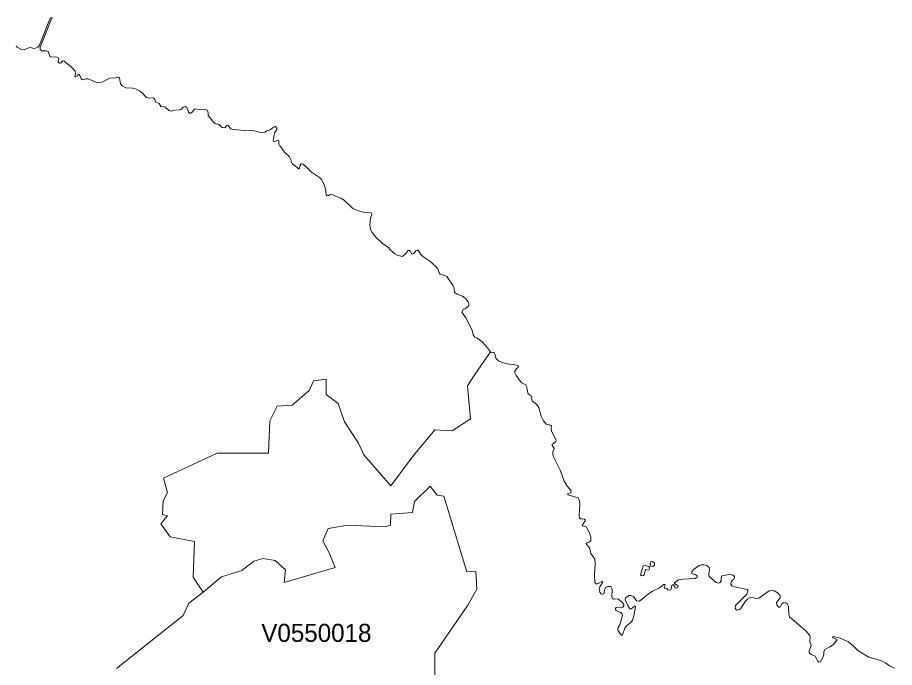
# Model space of a CAD drawing. Extents: x 369010 to 735936, y 6377141 to 6616555.
# Drawn here: x 440462 to 445317, y 6492936 to 6496537 of the extents above; entities that cross this region are included whole.
import ezdxf
from ezdxf.enums import TextEntityAlignment as Align

# ---------------------------------------------------------------- set-up
doc = ezdxf.new("R2010")
doc.units = 0
doc.header["$LTSCALE"] = 40
doc.layers.add('3', color=7, linetype='Continuous', lineweight=13)
doc.layers.add('4', color=7, linetype='Continuous')

msp = doc.modelspace()

# ---------------------------------------------------------------- linework, layer by layer
at = {"layer": '3'}
for points in [[(440645.3, 6496319.59), (440640.83, 6496323.06), (440630.74, 6496349.21), (440622.13, 6496351.86), (440595.65, 6496352.69), (440586.22, 6496360.14), (440587.87, 6496372.38), (440649.11, 6496528.45), (440653.41, 6496531.27), (440653.91, 6496534.91), (440649.77, 6496536.56), (440641.66, 6496533.25), (440581.09, 6496378.84), (440574.3, 6496373.05), (440556.26, 6496365.6), (440546.66, 6496365.93), (440532.43, 6496370.23), (440518.36, 6496367.25), (440498.33, 6496358.48), (440484.1, 6496359.14), (440460.1, 6496372.22), (440455.14, 6496377.18)], [(441928.95, 6495804.71), (441918.69, 6495824.73), (441911.57, 6495825.39), (441908.26, 6495833.67), (441909.26, 6495851.38), (441907.27, 6495854.85), (441901.81, 6495857.5), (441886.42, 6495849.72), (441877.64, 6495851.71), (441885.42, 6495895.24), (441898.33, 6495915.59), (441898, 6495924.37), (441890.55, 6495932.14), (441882.11, 6495931.81), (441863.08, 6495916.59), (441851.49, 6495911.46), (441840.74, 6495909.47), (441832.13, 6495902.02), (441820.38, 6495898.55), (441808.79, 6495898.88), (441764.61, 6495910.13), (441739.28, 6495908.48), (441656.2, 6495915.59), (441643.29, 6495920.72), (441627.24, 6495938.93), (441620.78, 6495938.27), (441610.02, 6495925.36), (441593.97, 6495928.17), (441578.58, 6495943.4), (441554.91, 6495949.85), (441548.29, 6495954.32), (441517.34, 6495993.71), (441516.68, 6496009.43), (441513.7, 6496021.35), (441501.45, 6496029.13), (441470.5, 6496027.14), (441444.35, 6496029.79), (441437.57, 6496025.49), (441430.29, 6496014.23), (441421.18, 6496005.96), (441413.41, 6496007.45), (441409.27, 6496012.08), (441399.34, 6496038.07), (441392.22, 6496043.36), (441384.77, 6496042.7), (441379.31, 6496039.72), (441367.06, 6496026.81), (441358.29, 6496024.33), (441332.47, 6496023.01), (441314.77, 6496018.54), (441300.37, 6496022.34), (441279.68, 6496040.71), (441270.74, 6496043.03), (441256.84, 6496042.7), (441245.92, 6496060.08), (441227.38, 6496068.52), (441222.91, 6496082.26), (441216.79, 6496090.7), (441207.52, 6496091.69), (441193.95, 6496089.37), (441175.91, 6496094.17), (441168.13, 6496100.3), (441154.56, 6496117.18), (441136.85, 6496130.58), (441124.27, 6496137.37), (441100.77, 6496145.81), (441062.37, 6496147.13), (441041.19, 6496158.06), (441031.75, 6496169.97), (441027.28, 6496201.92), (441021.16, 6496206.05), (441006.93, 6496202.58), (440972.17, 6496201.25), (440930.3, 6496177.75), (440910.27, 6496174.44), (440890.91, 6496179.9), (440852.18, 6496196.45), (440838.11, 6496197.45), (440824.87, 6496192.15), (440817.76, 6496192.81), (440813.29, 6496198.27), (440808.32, 6496211.18), (440800.38, 6496220.29), (440796.41, 6496220.29), (440791.28, 6496211.51), (440782.01, 6496208.04), (440779.36, 6496212.51), (440784.49, 6496232.53), (440781.01, 6496239.32), (440760, 6496261.17), (440720.77, 6496295.43), (440712.99, 6496296.09), (440701.41, 6496285), (440694.95, 6496283.84), (440687.17, 6496289.3), (440686.18, 6496293.77), (440690.15, 6496307.01), (440689.16, 6496313.8), (440680.06, 6496317.27), (440645.3, 6496319.59)], [(442170.92, 6494448.4), (442237.62, 6494397.26), (442271.71, 6494295.81), (442349.5, 6494178.63), (442378.96, 6494113.92), (442528.74, 6493942.62), (442655.02, 6494110.44), (442771.7, 6494252.94), (442867.69, 6494247.64), (442969.97, 6494313.68), (442953.75, 6494496.4), (442989.33, 6494553.99), (443079.87, 6494684.74), (443080.03, 6494685.07), (443063.81, 6494706.92), (443037.66, 6494735.22), (443009.2, 6494759.88), (442991.98, 6494766.33), (442992.31, 6494771.13), (442988.51, 6494773.12), (442984.87, 6494778.58), (442979.74, 6494803.74), (442944.81, 6494872.26), (442922.31, 6494903.87), (442930.58, 6494920.42), (442942.33, 6494924.89), (442959.71, 6494938.79), (442960.7, 6494952.36), (442957.39, 6494960.8), (442944.81, 6494978.18), (442928.76, 6494991.25), (442895.16, 6495004.83), (442884.41, 6495011.61), (442881.26, 6495017.07), (442877.95, 6495042.23), (442874.47, 6495050.67), (442839.22, 6495101.98), (442818.87, 6495111.41), (442802.65, 6495114.55), (442796.85, 6495122.33), (442789.07, 6495143.68), (442778.48, 6495157.92), (442745.22, 6495186.05), (442705.16, 6495212.53), (442694.08, 6495224.45), (442680.5, 6495247.12), (442674.38, 6495248.12), (442669.58, 6495246.46), (442655.68, 6495229.25), (442646.91, 6495226.1), (442642.77, 6495227.1), (442637.31, 6495241.33), (442628.87, 6495248.12), (442624.07, 6495246.46), (442611.99, 6495228.75), (442592.62, 6495212.86), (442567.47, 6495218.66), (442550.58, 6495227.76), (442524.43, 6495250.27), (442516.99, 6495260.03), (442480.91, 6495287.17), (442444.66, 6495320.77), (442424.97, 6495345.27), (442416.86, 6495362.15), (442411.73, 6495387.97), (442416.19, 6495424.21), (442423.31, 6495445.56), (442419.17, 6495454.17), (442376.8, 6495458.14), (442349.66, 6495464.93), (442322.52, 6495476.51), (442312.92, 6495483.3), (442270.55, 6495525), (442252.68, 6495536.26), (442225.53, 6495545.36), (442207.49, 6495554.96), (442192.27, 6495555.62), (442184.32, 6495550.16), (442176.21, 6495549.5), (442170.09, 6495553.97), (442168.1, 6495565.72), (442169.76, 6495582.43), (442158.67, 6495616.03), (442144.77, 6495639.7), (442134.51, 6495649.96), (442089.32, 6495679.42), (442065.66, 6495703.58), (442042.65, 6495723.28), (442032.06, 6495725.26), (442024.28, 6495714.67), (442022.96, 6495702.09), (442019.15, 6495699.11), (442015.01, 6495699.45), (441999.46, 6495715), (441984.56, 6495723.28), (441979.43, 6495734.37), (441975.13, 6495750.42), (441966.85, 6495764.32), (441941.03, 6495787.99), (441928.95, 6495804.71)], [(443080.03, 6494685.07), (443079.87, 6494684.74), (442989.33, 6494553.99), (442953.75, 6494496.4), (442969.97, 6494313.68), (442867.69, 6494247.64), (442771.7, 6494252.94), (442655.02, 6494110.44), (442528.74, 6493942.62), (442378.96, 6494113.92), (442349.5, 6494178.63), (442271.71, 6494295.81), (442237.62, 6494397.26), (442170.92, 6494448.4), (442170.75, 6494532.15), (442100.08, 6494524.53), (442076.75, 6494470.74), (441982.9, 6494388.49), (441899.99, 6494383.85), (441859.6, 6494301.43), (441851.83, 6494123.35), (441714.46, 6494123.35), (441566.83, 6494123.35), (441269.25, 6493984.16), (441291.26, 6493904.39), (441267.6, 6493858.21), (441264.95, 6493783.9), (441291.43, 6493775.63), (441256.01, 6493731.77), (441306.82, 6493658.78), (441442.2, 6493633.62), (441435.09, 6493435.35), (441490.53, 6493353.43), (441590.49, 6493437.17), (441704.53, 6493473.25), (441769.57, 6493524.23), (441820.38, 6493539.12), (441887.74, 6493528.86), (441945.17, 6493476.06), (441937.56, 6493405.56), (442220.73, 6493489.97), (442186.64, 6493570.57), (442151.72, 6493637.93), (442180.85, 6493706.45), (442290.41, 6493723.66), (442494.64, 6493715.05), (442527.41, 6493724.65), (442529.4, 6493784.23), (442648.4, 6493794.33), (442660.64, 6493855.23), (442746.71, 6493940.14), (442784.94, 6493889.82), (442822.67, 6493884.69), (442949.61, 6493464.64), (442999.1, 6493467.29), (443004.89, 6493369.15), (442954.58, 6493280.27), (442772.36, 6493015.63), (442771.86, 6492843.51)], [(443283.1, 6494472.23), (443281.78, 6494490.44), (443276.32, 6494501.69), (443253.48, 6494512.95), (443246.03, 6494520.06), (443222.03, 6494553.66), (443214.42, 6494568.56), (443214.92, 6494577.33), (443223.36, 6494588.91), (443234.61, 6494598.68), (443235.94, 6494603.81), (443233.78, 6494608.28), (443214.42, 6494613.08), (443172.38, 6494617.71), (443147.06, 6494624.5), (443124.88, 6494635.09), (443112.3, 6494645.85), (443107.34, 6494666.2), (443101.55, 6494679.94), (443098.07, 6494681.26), (443084.17, 6494679.78), (443080.03, 6494685.07)], [(441010.4, 6492930.73), (441379.15, 6493224.5), (441410.1, 6493292.69), (441490.53, 6493353.43), (441435.09, 6493435.35), (441442.2, 6493633.62), (441306.82, 6493658.78), (441256.01, 6493731.77), (441291.43, 6493775.63), (441264.95, 6493783.9), (441267.6, 6493858.21), (441291.26, 6493904.39), (441269.25, 6493984.16), (441566.83, 6494123.35), (441714.46, 6494123.35), (441851.83, 6494123.35), (441859.6, 6494301.43), (441899.99, 6494383.85), (441982.9, 6494388.49), (442076.75, 6494470.74), (442100.08, 6494524.53), (442170.75, 6494532.15), (442170.92, 6494448.4)], [(443867, 6493198.02), (443857.4, 6493183.95), (443832.74, 6493165.58), (443823.81, 6493154.16), (443812.22, 6493116.09), (443808.75, 6493113.61), (443799.64, 6493120.23), (443785.41, 6493142.91), (443787.73, 6493159.62), (443796.66, 6493171.04), (443811.72, 6493223.51), (443807.42, 6493234.43), (443800.14, 6493240.88), (443776.47, 6493251.48), (443772.33, 6493257.76), (443772.33, 6493262.23), (443775.81, 6493267.7), (443803.28, 6493265.54), (443814.21, 6493270.51), (443818.68, 6493279.94), (443818.68, 6493284.41), (443811.72, 6493294.01), (443788.55, 6493315.03), (443774.82, 6493316.68), (443760.75, 6493313.71), (443756.94, 6493317.02), (443752.47, 6493326.28), (443754.46, 6493366.83), (443752.8, 6493373.95), (443746.02, 6493383.55), (443728.81, 6493385.2), (443718.21, 6493378.75), (443712.42, 6493364.02), (443708.62, 6493344.49), (443695.87, 6493341.68), (443685.94, 6493352.76), (443682.47, 6493366.83), (443685.61, 6493383.22), (443701.33, 6493405.56), (443701, 6493411.68), (443696.53, 6493412.35), (443672.2, 6493398.61), (443662.94, 6493398.77), (443658.14, 6493406.55), (443656.81, 6493447.6), (443659.63, 6493510.82), (443657.81, 6493535.81), (443636.95, 6493567.75), (443629.67, 6493599.2), (443611.63, 6493616.41), (443610.8, 6493622.87), (443616.1, 6493627), (443629.67, 6493631.47), (443636.29, 6493636.93), (443636.29, 6493657.46), (443627.35, 6493685.59), (443609.48, 6493715.38), (443588.96, 6493720.35), (443589.29, 6493726.8), (443604.35, 6493748.32), (443605.01, 6493752.79), (443601.7, 6493757.26), (443590.28, 6493760.07), (443577.37, 6493760.07), (443572.57, 6493764.54), (443571.74, 6493778.28), (443575.88, 6493835.87), (443573.56, 6493861.52), (443565.95, 6493874.93), (443508.36, 6493892.31), (443509.02, 6493898.93), (443525.24, 6493904.06), (443527.22, 6493914.65), (443507.36, 6493937.66), (443489.16, 6493967.78), (443467.31, 6494025.37), (443430.9, 6494098.36), (443426.6, 6494115.24), (443425.93, 6494131.63), (443434.04, 6494144.7), (443433.71, 6494149.17), (443422.13, 6494165.55), (443422.13, 6494170.52), (443441.16, 6494186.57), (443443.81, 6494193.69), (443418.16, 6494246.98), (443417, 6494259.06), (443418.49, 6494273.63), (443413.36, 6494277.77), (443388.86, 6494283.23), (443373.97, 6494301.6), (443361.39, 6494328.74), (443347.82, 6494376.24), (443334.58, 6494394.45), (443311.9, 6494410.5), (443308.76, 6494420.27), (443309.58, 6494429.53), (443305.45, 6494440.62), (443288.9, 6494450.88), (443283.1, 6494472.23)], [(442771.86, 6492843.51), (442772.36, 6493015.63), (442954.58, 6493280.27), (443004.89, 6493369.15), (442999.1, 6493467.29), (442949.61, 6493464.64), (442822.67, 6493884.69), (442784.94, 6493889.82), (442746.71, 6493940.14), (442660.64, 6493855.23), (442648.4, 6493794.33), (442529.4, 6493784.23), (442527.41, 6493724.65), (442494.64, 6493715.05), (442290.41, 6493723.66), (442180.85, 6493706.45), (442151.72, 6493637.93), (442186.64, 6493570.57), (442220.73, 6493489.97), (441937.56, 6493405.56), (441945.17, 6493476.06), (441887.74, 6493528.86), (441820.38, 6493539.12), (441769.57, 6493524.23), (441704.53, 6493473.25), (441590.49, 6493437.17), (441490.53, 6493353.43), (441410.1, 6493292.69), (441379.15, 6493224.5), (441010.4, 6492930.73)], [(444724.15, 6493286.23), (444716.2, 6493293.02), (444703.63, 6493295.17), (444693.36, 6493288.22), (444684.76, 6493270.34), (444674.83, 6493269.02), (444665.56, 6493283.09), (444664.24, 6493295.5), (444684.43, 6493321.48), (444685.09, 6493332.41), (444673.01, 6493347.96), (444652.15, 6493359.88), (444642.22, 6493362.36), (444622.69, 6493359.88), (444565.43, 6493318.84), (444547.22, 6493317.02), (444538.62, 6493321.48), (444519.42, 6493322.48), (444504.03, 6493315.03), (444493.1, 6493302.95), (444464.64, 6493260.74), (444459.18, 6493256.44), (444441.96, 6493253.63), (444435.18, 6493264.55), (444437.49, 6493279.94), (444499.56, 6493342.34), (444506.18, 6493355.08), (444506.18, 6493363.36), (444500.88, 6493367.83), (444434.85, 6493381.56), (444416.31, 6493388.35), (444410.85, 6493397.95), (444410.52, 6493404.9), (444418.3, 6493417.15), (444428.56, 6493425.42), (444431.7, 6493432.21), (444431.7, 6493437.67), (444424.92, 6493447.27), (444401.58, 6493451.07), (444360.7, 6493443.63), (444357.23, 6493430.88), (444357.23, 6493415.49), (444352.09, 6493405.56), (444344.32, 6493402.42), (444330.58, 6493405.56), (444293.18, 6493438), (444290.03, 6493443.63), (444289.37, 6493454.55), (444292.51, 6493477.55), (444290.53, 6493489.8), (444277.78, 6493500.06), (444262.72, 6493504.2), (444247.33, 6493503.87), (444235.58, 6493500.23), (444205.46, 6493477.89), (444195.2, 6493466.47), (444196.19, 6493456.54), (444199.5, 6493453.56), (444214.06, 6493451.07), (444225.32, 6493442.8), (444225.65, 6493436.34), (444214.06, 6493427.74), (444147.53, 6493425.75), (444120.72, 6493420.95), (444099.54, 6493403.74), (444099.54, 6493401.75), (444117.91, 6493388.02), (444119.4, 6493384.21), (444117.58, 6493379.08), (444107.98, 6493374.94), (444101.19, 6493377.42), (444100.86, 6493384.54), (444094.4, 6493393.81), (444086.46, 6493393.48), (444078.52, 6493365.34), (444075.21, 6493363.36), (444062.13, 6493366.5), (444057.66, 6493373.29), (444042.93, 6493374.61), (444048.39, 6493393.48), (444045.25, 6493396.29), (444037.8, 6493395.96), (444015.79, 6493376.76), (443978.06, 6493358.23), (443955.38, 6493343.17), (443905.4, 6493302.62), (443888.52, 6493305.76), (443872.46, 6493329.76), (443857.73, 6493334.56), (443847.14, 6493334.23), (443827.94, 6493320.82), (443825.46, 6493309.9), (443842.01, 6493274.81), (443851.61, 6493260.41), (443856.74, 6493259.09), (443877.26, 6493275.14), (443881.73, 6493275.14), (443883.39, 6493270.34), (443874.12, 6493221.02), (443867, 6493198.02)], [(445317.31, 6492932.05), (445290.17, 6492944.96), (445268.66, 6492959.69), (445241.18, 6492973.93), (445174.65, 6492992.3), (445114.08, 6493029.04), (445089.75, 6493054.36), (445063.6, 6493077.37), (445017.26, 6493098.22), (444978.53, 6493108.15), (444975.05, 6493102.03), (444995.41, 6493093.09), (444997.39, 6493090.44), (444997.73, 6493083.16), (444994.75, 6493082.5), (444978.86, 6493062.97), (444959, 6493049.89), (444932.35, 6493035.99), (444926.89, 6493022.58), (444926.72, 6493007.36), (444920.93, 6492991.3), (444905.87, 6492965.98), (444896.93, 6492967.31), (444890.48, 6492972.44), (444884.02, 6492988.16), (444877.74, 6492997.43), (444855.56, 6493007.36), (444845.96, 6493015.96), (444844.47, 6493028.05), (444855.23, 6493054.69), (444855.06, 6493064.62), (444849.27, 6493077.7), (444848.28, 6493085.31), (444850.43, 6493100.7), (444849.6, 6493111.96), (444825.93, 6493137.77), (444736.56, 6493216.89), (444732.09, 6493232.44), (444730.77, 6493270.84), (444724.15, 6493286.23)]]:
    msp.add_lwpolyline(points, dxfattribs=at)
for points in [[(443978.39, 6493523.73), (443966.8, 6493520.75), (443963.99, 6493509.66), (443967.79, 6493497.75), (443978.72, 6493495.26), (443987.99, 6493501.88), (443987.99, 6493513.47)], [(443936.35, 6493500.06), (443926.58, 6493499.07), (443910.86, 6493449.42), (443916.65, 6493442.8), (443927.41, 6493445.28), (443933.54, 6493452.89), (443936.18, 6493474.08), (443940.65, 6493478.22), (443956.54, 6493475.4), (443961.34, 6493481.69), (443960.18, 6493491.29), (443956.54, 6493495.26)]]:
    msp.add_lwpolyline(points, close=True, dxfattribs=at)

# ---------------------------------------------------------------- texts
at = {"layer": '4'}
msp.add_text('V0550018', height=100, dxfattribs=at).set_placement((442116.47, 6493077.39), align=Align.CENTER)

doc.saveas('drawing.dxf')
